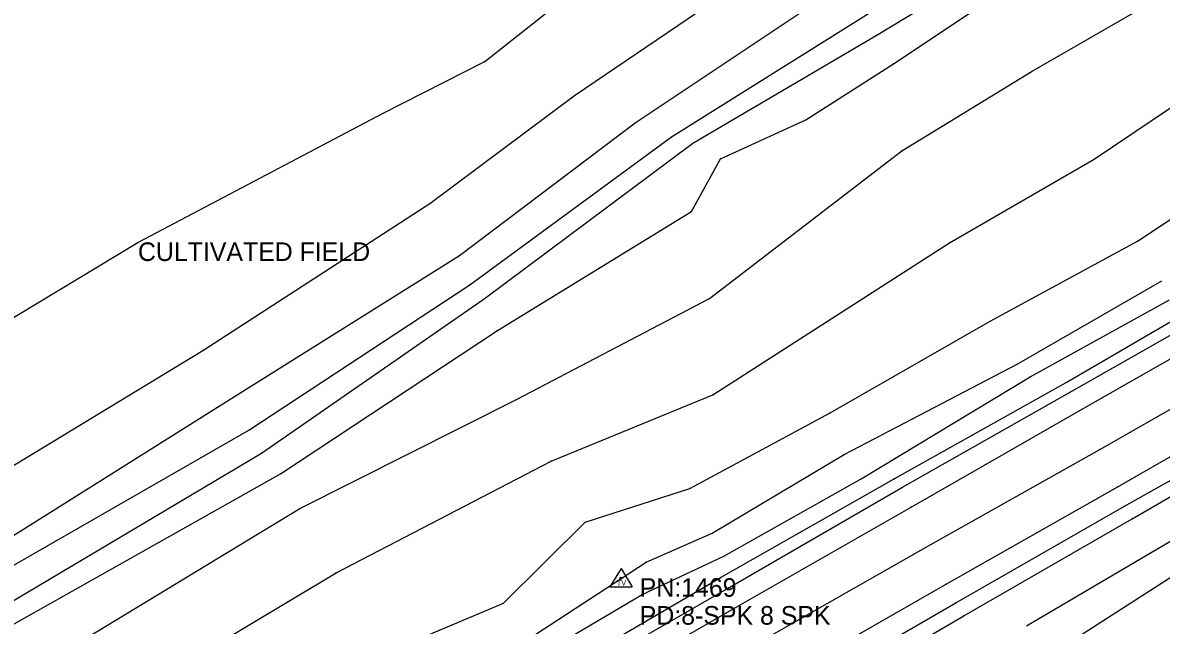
# Model space of a CAD drawing. Extents: x 1419505 to 1434054, y 1956910 to 1968644.
# Drawn here: x 1422716.6 to 1423022.6, y 1958878 to 1959040 of the extents above; entities that cross this region are included whole.
import ezdxf

# ---------------------------------------------------------------- set-up
doc = ezdxf.new("R2010")
doc.units = 0
for name, color, linetype in [('S_BREAKLINE', 7, 'Continuous'), ('S_DITCHLINE', 7, 'Continuous'), ('S_EDGE_PAVEMENT', 7, 'Continuous'), ('S_GRD_PT_SYM', 7, 'Continuous'), ('S_MSC_PT_SYM', 7, 'Continuous'), ('S_PAVEMENT_CROWN', 7, 'Continuous'), ('S_RDW_PT_SYM', 7, 'Continuous'), ('S_SECONDARY_CTL', 7, 'Continuous'), ('S_SECONDARY_CTL_ANNOT', 7, 'Continuous'), ('S_SHOULDER', 7, 'Continuous'), ('S_SURVEY_TEXT_ANNOT', 7, 'Continuous')]:
    doc.layers.add(name, color=color, linetype=linetype)

msp = doc.modelspace()

# ---------------------------------------------------------------- linework, layer by layer
at = {"layer": 'S_BREAKLINE'}
for p, q in [((1422840.7776, 1959029.6612), (1422909.3401, 1959083.9587)), ((1422864.9112, 1959020.4656), (1422927.6052, 1959063.1023)), ((1422881.2152, 1959013.1311), (1422938.3659, 1959051.3316)), ((1422950.6087, 1959028.9581), (1422978.6695, 1959047.6883)), ((1422987.9141, 1959027.032), (1423022.4534, 1959046.9853)), ((1422813.5029, 1959015.6943), (1422840.7776, 1959029.6612)), ((1422927.0872, 1959013.9382), (1422950.6087, 1959028.9581)), ((1422952.8299, 1959005.5936), (1422987.9141, 1959027.032)), ((1423004.5812, 1959003.3335), (1423034.3291, 1959023.3928)), ((1422826.0327, 1958991.4147), (1422864.9112, 1959020.4656)), ((1422747.5446, 1958980.981), (1422813.5029, 1959015.6943)), ((1422833.9622, 1958977.4928), (1422881.2152, 1959013.1311)), ((1422904.0857, 1959003.4215), (1422927.0872, 1959013.9382)), ((1422901.1935, 1958965.9291), (1422952.8299, 1959005.5936)), ((1422896.3542, 1958989.3066), (1422904.0857, 1959003.4215)), ((1422965.6687, 1958980.83), (1423004.5812, 1959003.3335)), ((1423016.171, 1958981.2871), (1423045.3818, 1959000.6413)), ((1422764.9527, 1958951.8852), (1422826.0327, 1958991.4147)), ((1422844.1579, 1958957.3105), (1422896.3542, 1958989.3066)), ((1422680.8713, 1958940.6924), (1422747.5446, 1958980.981)), ((1422902.0406, 1958939.9634), (1422965.6687, 1958980.83)), ((1422976.6254, 1958959.7677), (1423016.171, 1958981.2871)), ((1422772.8152, 1958939.0653), (1422833.9622, 1958977.4928)), ((1422983.9009, 1958948.2079), (1423022.7654, 1958970.6634)), ((1422997.0597, 1958943.3036), (1423043.5507, 1958970.5214)), ((1422849.3282, 1958938.7293), (1422901.1935, 1958965.9291)), ((1422987.3671, 1958944.8277), (1423024.7805, 1958965.546)), ((1422933.6196, 1958935.1441), (1422976.6254, 1958959.7677)), ((1422785.8341, 1958918.713), (1422844.1579, 1958957.3105)), ((1422696.1713, 1958910.1255), (1422764.9527, 1958951.8852)), ((1422937.3739, 1958923.9694), (1422983.9009, 1958948.2079)), ((1422941.9652, 1958917.4139), (1422987.3671, 1958944.8277)), ((1422950.8037, 1958917.4309), (1422997.0597, 1958943.3036)), ((1422704.0708, 1958895.8675), (1422772.8152, 1958939.0653)), ((1422791.0704, 1958909.4174), (1422849.3282, 1958938.7293)), ((1422858.6048, 1958922.1172), (1422902.0406, 1958939.9634)), ((1422895.8612, 1958914.7938), (1422933.6196, 1958935.1441)), ((1423014.7349, 1958906.6712), (1423063.781, 1958935.0261)), ((1422901.9166, 1958902.76), (1422937.3739, 1958923.9694)), ((1422800.7891, 1958892.1663), (1422858.6048, 1958922.1172)), ((1422714.3205, 1958878.4334), (1422785.8341, 1958918.713)), ((1422904.3137, 1958890.9922), (1422950.8037, 1958917.4309)), ((1422905.0308, 1958896.6186), (1422941.9652, 1958917.4139)), ((1422867.7834, 1958905.7492), (1422895.8612, 1958914.7938)), ((1422718.6307, 1958865.5316), (1422791.0704, 1958909.4174)), ((1422986.336, 1958877.8964), (1423041.4856, 1958910.3185)), ((1422845.759, 1958883.9798), (1422867.7834, 1958905.7492)), ((1422969.4989, 1958880.5795), (1423014.7349, 1958906.6712)), ((1422884.1034, 1958895.0085), (1422901.9166, 1958902.76)), ((1422990.4573, 1958868.6708), (1423043.8127, 1958903.008)), ((1422883.0484, 1958886.3259), (1422905.0308, 1958896.6186)), ((1422728.1394, 1958848.5945), (1422800.7891, 1958892.1663)), ((1422852.1924, 1958874.0641), (1422884.1034, 1958895.0085)), ((1422857.1067, 1958863.3734), (1422904.3137, 1958890.9922)), ((1422854.5305, 1958869.4648), (1422883.0484, 1958886.3259)), ((1422814.4259, 1958870.7569), (1422845.759, 1958883.9798)), ((1422923.458, 1958853.8008), (1422969.4989, 1958880.5795))]:
    msp.add_line(p, q, dxfattribs=at)
at = {"layer": 'S_DITCHLINE'}
for p, q in [((1422945.9684, 1959036.6096), (1422975.5353, 1959054.7468)), ((1422890.9719, 1959009.3679), (1422943.9453, 1959042.53)), ((1422896.7242, 1959007.7008), (1422945.9684, 1959036.6096)), ((1422836.7134, 1958969.5783), (1422890.9719, 1959009.3679)), ((1422840.5706, 1958965.7651), (1422896.7242, 1959007.7008)), ((1422777.3605, 1958930.4788), (1422836.7134, 1958969.5783)), ((1422780.7508, 1958924.2814), (1422840.5706, 1958965.7651)), ((1422706.752, 1958889.9102), (1422777.3605, 1958930.4788)), ((1422710.9763, 1958882.8447), (1422780.7508, 1958924.2814))]:
    msp.add_line(p, q, dxfattribs=at)
at = {"layer": 'S_EDGE_PAVEMENT'}
for p, q in [((1423000.534, 1958935.6891), (1423047.602, 1958962.5568)), ((1423010.6966, 1958915.1808), (1423058.3237, 1958942.5015)), ((1422955.329, 1958909.8164), (1423000.534, 1958935.6891)), ((1422964.5716, 1958888.9541), (1423010.6966, 1958915.1808)), ((1422908.352, 1958882.8477), (1422955.329, 1958909.8164)), ((1422918.8007, 1958862.7874), (1422964.5716, 1958888.9541)), ((1422859.7289, 1958855.0279), (1422908.352, 1958882.8477))]:
    msp.add_line(p, q, dxfattribs=at)
at = {"layer": 'S_GRD_PT_SYM'}
for points in [[(1422945.9684, 1959036.6096), (1422945.9684, 1959036.6596), (1422945.9684, 1959036.6096), (1422945.9184, 1959036.6096), (1422945.9684, 1959036.6096), (1422945.9684, 1959036.5596), (1422945.9684, 1959036.6096), (1422946.0184, 1959036.6096)], [(1422840.7776, 1959029.6612), (1422840.7776, 1959029.7112), (1422840.7776, 1959029.6612), (1422840.7276, 1959029.6612), (1422840.7776, 1959029.6612), (1422840.7776, 1959029.6112), (1422840.7776, 1959029.6612), (1422840.8276, 1959029.6612)], [(1422950.6087, 1959028.9581), (1422950.6087, 1959029.0081), (1422950.6087, 1959028.9581), (1422950.5587, 1959028.9581), (1422950.6087, 1959028.9581), (1422950.6087, 1959028.9081), (1422950.6087, 1959028.9581), (1422950.6587, 1959028.9581)], [(1422987.9141, 1959027.032), (1422987.9141, 1959027.082), (1422987.9141, 1959027.032), (1422987.8641, 1959027.032), (1422987.9141, 1959027.032), (1422987.9141, 1959026.982), (1422987.9141, 1959027.032), (1422987.9641, 1959027.032)], [(1422864.9112, 1959020.4656), (1422864.9112, 1959020.5156), (1422864.9112, 1959020.4656), (1422864.8612, 1959020.4656), (1422864.9112, 1959020.4656), (1422864.9112, 1959020.4156), (1422864.9112, 1959020.4656), (1422864.9612, 1959020.4656)], [(1422813.5029, 1959015.6943), (1422813.5029, 1959015.7443), (1422813.5029, 1959015.6943), (1422813.4529, 1959015.6943), (1422813.5029, 1959015.6943), (1422813.5029, 1959015.6443), (1422813.5029, 1959015.6943), (1422813.5529, 1959015.6943)], [(1422881.2152, 1959013.1311), (1422881.2152, 1959013.1811), (1422881.2152, 1959013.1311), (1422881.1652, 1959013.1311), (1422881.2152, 1959013.1311), (1422881.2152, 1959013.0811), (1422881.2152, 1959013.1311), (1422881.2652, 1959013.1311)], [(1422927.0872, 1959013.9382), (1422927.0872, 1959013.9882), (1422927.0872, 1959013.9382), (1422927.0372, 1959013.9382), (1422927.0872, 1959013.9382), (1422927.0872, 1959013.8882), (1422927.0872, 1959013.9382), (1422927.1372, 1959013.9382)], [(1422890.9719, 1959009.3679), (1422890.9719, 1959009.4179), (1422890.9719, 1959009.3679), (1422890.9219, 1959009.3679), (1422890.9719, 1959009.3679), (1422890.9719, 1959009.3179), (1422890.9719, 1959009.3679), (1422891.0219, 1959009.3679)], [(1422896.7242, 1959007.7008), (1422896.7242, 1959007.7508), (1422896.7242, 1959007.7008), (1422896.6742, 1959007.7008), (1422896.7242, 1959007.7008), (1422896.7242, 1959007.6508), (1422896.7242, 1959007.7008), (1422896.7742, 1959007.7008)], [(1422952.8299, 1959005.5936), (1422952.8299, 1959005.6436), (1422952.8299, 1959005.5936), (1422952.7799, 1959005.5936), (1422952.8299, 1959005.5936), (1422952.8299, 1959005.5436), (1422952.8299, 1959005.5936), (1422952.8799, 1959005.5936)], [(1422904.0857, 1959003.4215), (1422904.0857, 1959003.4715), (1422904.0857, 1959003.4215), (1422904.0357, 1959003.4215), (1422904.0857, 1959003.4215), (1422904.0857, 1959003.3715), (1422904.0857, 1959003.4215), (1422904.1357, 1959003.4215)], [(1423004.5812, 1959003.3335), (1423004.5812, 1959003.3835), (1423004.5812, 1959003.3335), (1423004.5312, 1959003.3335), (1423004.5812, 1959003.3335), (1423004.5812, 1959003.2835), (1423004.5812, 1959003.3335), (1423004.6312, 1959003.3335)], [(1422826.0327, 1958991.4147), (1422826.0327, 1958991.4647), (1422826.0327, 1958991.4147), (1422825.9827, 1958991.4147), (1422826.0327, 1958991.4147), (1422826.0327, 1958991.3647), (1422826.0327, 1958991.4147), (1422826.0827, 1958991.4147)], [(1422896.3542, 1958989.3066), (1422896.3542, 1958989.3566), (1422896.3542, 1958989.3066), (1422896.3042, 1958989.3066), (1422896.3542, 1958989.3066), (1422896.3542, 1958989.2566), (1422896.3542, 1958989.3066), (1422896.4042, 1958989.3066)], [(1422747.5446, 1958980.981), (1422747.5446, 1958981.031), (1422747.5446, 1958980.981), (1422747.4946, 1958980.981), (1422747.5446, 1958980.981), (1422747.5446, 1958980.931), (1422747.5446, 1958980.981), (1422747.5946, 1958980.981)], [(1422965.6687, 1958980.83), (1422965.6687, 1958980.88), (1422965.6687, 1958980.83), (1422965.6187, 1958980.83), (1422965.6687, 1958980.83), (1422965.6687, 1958980.78), (1422965.6687, 1958980.83), (1422965.7187, 1958980.83)], [(1423016.171, 1958981.2871), (1423016.171, 1958981.3371), (1423016.171, 1958981.2871), (1423016.121, 1958981.2871), (1423016.171, 1958981.2871), (1423016.171, 1958981.2371), (1423016.171, 1958981.2871), (1423016.221, 1958981.2871)], [(1422833.9622, 1958977.4928), (1422833.9622, 1958977.5428), (1422833.9622, 1958977.4928), (1422833.9122, 1958977.4928), (1422833.9622, 1958977.4928), (1422833.9622, 1958977.4428), (1422833.9622, 1958977.4928), (1422834.0122, 1958977.4928)], [(1422836.7134, 1958969.5783), (1422836.7134, 1958969.6283), (1422836.7134, 1958969.5783), (1422836.6634, 1958969.5783), (1422836.7134, 1958969.5783), (1422836.7134, 1958969.5283), (1422836.7134, 1958969.5783), (1422836.7634, 1958969.5783)], [(1422840.5706, 1958965.7651), (1422840.5706, 1958965.8151), (1422840.5706, 1958965.7651), (1422840.5206, 1958965.7651), (1422840.5706, 1958965.7651), (1422840.5706, 1958965.7151), (1422840.5706, 1958965.7651), (1422840.6206, 1958965.7651)], [(1422901.1935, 1958965.9291), (1422901.1935, 1958965.9791), (1422901.1935, 1958965.9291), (1422901.1435, 1958965.9291), (1422901.1935, 1958965.9291), (1422901.1935, 1958965.8791), (1422901.1935, 1958965.9291), (1422901.2435, 1958965.9291)], [(1422976.6254, 1958959.7677), (1422976.6254, 1958959.8177), (1422976.6254, 1958959.7677), (1422976.5754, 1958959.7677), (1422976.6254, 1958959.7677), (1422976.6254, 1958959.7177), (1422976.6254, 1958959.7677), (1422976.6754, 1958959.7677)], [(1422844.1579, 1958957.3105), (1422844.1579, 1958957.3605), (1422844.1579, 1958957.3105), (1422844.1079, 1958957.3105), (1422844.1579, 1958957.3105), (1422844.1579, 1958957.2605), (1422844.1579, 1958957.3105), (1422844.2079, 1958957.3105)], [(1422764.9527, 1958951.8852), (1422764.9527, 1958951.9352), (1422764.9527, 1958951.8852), (1422764.9027, 1958951.8852), (1422764.9527, 1958951.8852), (1422764.9527, 1958951.8352), (1422764.9527, 1958951.8852), (1422765.0027, 1958951.8852)], [(1422983.9009, 1958948.2079), (1422983.9009, 1958948.2579), (1422983.9009, 1958948.2079), (1422983.8509, 1958948.2079), (1422983.9009, 1958948.2079), (1422983.9009, 1958948.1579), (1422983.9009, 1958948.2079), (1422983.9509, 1958948.2079)], [(1422987.3671, 1958944.8277), (1422987.3671, 1958944.8777), (1422987.3671, 1958944.8277), (1422987.3171, 1958944.8277), (1422987.3671, 1958944.8277), (1422987.3671, 1958944.7777), (1422987.3671, 1958944.8277), (1422987.4171, 1958944.8277)], [(1422997.0597, 1958943.3036), (1422997.0597, 1958943.3536), (1422997.0597, 1958943.3036), (1422997.0097, 1958943.3036), (1422997.0597, 1958943.3036), (1422997.0597, 1958943.2536), (1422997.0597, 1958943.3036), (1422997.1097, 1958943.3036)], [(1422772.8152, 1958939.0653), (1422772.8152, 1958939.1153), (1422772.8152, 1958939.0653), (1422772.7652, 1958939.0653), (1422772.8152, 1958939.0653), (1422772.8152, 1958939.0153), (1422772.8152, 1958939.0653), (1422772.8652, 1958939.0653)], [(1422849.3282, 1958938.7293), (1422849.3282, 1958938.7793), (1422849.3282, 1958938.7293), (1422849.2782, 1958938.7293), (1422849.3282, 1958938.7293), (1422849.3282, 1958938.6793), (1422849.3282, 1958938.7293), (1422849.3782, 1958938.7293)], [(1422902.0406, 1958939.9634), (1422902.0406, 1958940.0134), (1422902.0406, 1958939.9634), (1422901.9906, 1958939.9634), (1422902.0406, 1958939.9634), (1422902.0406, 1958939.9134), (1422902.0406, 1958939.9634), (1422902.0906, 1958939.9634)], [(1422933.6196, 1958935.1441), (1422933.6196, 1958935.1941), (1422933.6196, 1958935.1441), (1422933.5696, 1958935.1441), (1422933.6196, 1958935.1441), (1422933.6196, 1958935.0941), (1422933.6196, 1958935.1441), (1422933.6696, 1958935.1441)], [(1422777.3605, 1958930.4788), (1422777.3605, 1958930.5288), (1422777.3605, 1958930.4788), (1422777.3105, 1958930.4788), (1422777.3605, 1958930.4788), (1422777.3605, 1958930.4288), (1422777.3605, 1958930.4788), (1422777.4105, 1958930.4788)], [(1422780.7508, 1958924.2814), (1422780.7508, 1958924.3314), (1422780.7508, 1958924.2814), (1422780.7008, 1958924.2814), (1422780.7508, 1958924.2814), (1422780.7508, 1958924.2314), (1422780.7508, 1958924.2814), (1422780.8008, 1958924.2814)], [(1422937.3739, 1958923.9694), (1422937.3739, 1958924.0194), (1422937.3739, 1958923.9694), (1422937.3239, 1958923.9694), (1422937.3739, 1958923.9694), (1422937.3739, 1958923.9194), (1422937.3739, 1958923.9694), (1422937.4239, 1958923.9694)], [(1422858.6048, 1958922.1172), (1422858.6048, 1958922.1672), (1422858.6048, 1958922.1172), (1422858.5548, 1958922.1172), (1422858.6048, 1958922.1172), (1422858.6048, 1958922.0672), (1422858.6048, 1958922.1172), (1422858.6548, 1958922.1172)], [(1422785.8341, 1958918.713), (1422785.8341, 1958918.763), (1422785.8341, 1958918.713), (1422785.7841, 1958918.713), (1422785.8341, 1958918.713), (1422785.8341, 1958918.663), (1422785.8341, 1958918.713), (1422785.8841, 1958918.713)], [(1422941.9652, 1958917.4139), (1422941.9652, 1958917.4639), (1422941.9652, 1958917.4139), (1422941.9152, 1958917.4139), (1422941.9652, 1958917.4139), (1422941.9652, 1958917.3639), (1422941.9652, 1958917.4139), (1422942.0152, 1958917.4139)], [(1422950.8037, 1958917.4309), (1422950.8037, 1958917.4809), (1422950.8037, 1958917.4309), (1422950.7537, 1958917.4309), (1422950.8037, 1958917.4309), (1422950.8037, 1958917.3809), (1422950.8037, 1958917.4309), (1422950.8537, 1958917.4309)], [(1422895.8612, 1958914.7938), (1422895.8612, 1958914.8438), (1422895.8612, 1958914.7938), (1422895.8112, 1958914.7938), (1422895.8612, 1958914.7938), (1422895.8612, 1958914.7438), (1422895.8612, 1958914.7938), (1422895.9112, 1958914.7938)], [(1422791.0704, 1958909.4174), (1422791.0704, 1958909.4674), (1422791.0704, 1958909.4174), (1422791.0204, 1958909.4174), (1422791.0704, 1958909.4174), (1422791.0704, 1958909.3674), (1422791.0704, 1958909.4174), (1422791.1204, 1958909.4174)], [(1422867.7834, 1958905.7492), (1422867.7834, 1958905.7992), (1422867.7834, 1958905.7492), (1422867.7334, 1958905.7492), (1422867.7834, 1958905.7492), (1422867.7834, 1958905.6992), (1422867.7834, 1958905.7492), (1422867.8334, 1958905.7492)], [(1423014.7349, 1958906.6712), (1423014.7349, 1958906.7212), (1423014.7349, 1958906.6712), (1423014.6849, 1958906.6712), (1423014.7349, 1958906.6712), (1423014.7349, 1958906.6212), (1423014.7349, 1958906.6712), (1423014.7849, 1958906.6712)], [(1422901.9166, 1958902.76), (1422901.9166, 1958902.81), (1422901.9166, 1958902.76), (1422901.8666, 1958902.76), (1422901.9166, 1958902.76), (1422901.9166, 1958902.71), (1422901.9166, 1958902.76), (1422901.9666, 1958902.76)], [(1422905.0308, 1958896.6186), (1422905.0308, 1958896.6686), (1422905.0308, 1958896.6186), (1422904.9808, 1958896.6186), (1422905.0308, 1958896.6186), (1422905.0308, 1958896.5686), (1422905.0308, 1958896.6186), (1422905.0808, 1958896.6186)], [(1422800.7891, 1958892.1663), (1422800.7891, 1958892.2163), (1422800.7891, 1958892.1663), (1422800.7391, 1958892.1663), (1422800.7891, 1958892.1663), (1422800.7891, 1958892.1163), (1422800.7891, 1958892.1663), (1422800.8391, 1958892.1663)], [(1422884.1034, 1958895.0085), (1422884.1034, 1958895.0585), (1422884.1034, 1958895.0085), (1422884.0534, 1958895.0085), (1422884.1034, 1958895.0085), (1422884.1034, 1958894.9585), (1422884.1034, 1958895.0085), (1422884.1534, 1958895.0085)], [(1422904.3137, 1958890.9922), (1422904.3137, 1958891.0422), (1422904.3137, 1958890.9922), (1422904.2637, 1958890.9922), (1422904.3137, 1958890.9922), (1422904.3137, 1958890.9422), (1422904.3137, 1958890.9922), (1422904.3637, 1958890.9922)], [(1422883.0484, 1958886.3259), (1422883.0484, 1958886.3759), (1422883.0484, 1958886.3259), (1422882.9984, 1958886.3259), (1422883.0484, 1958886.3259), (1422883.0484, 1958886.2759), (1422883.0484, 1958886.3259), (1422883.0984, 1958886.3259)], [(1422845.759, 1958883.9798), (1422845.759, 1958884.0298), (1422845.759, 1958883.9798), (1422845.709, 1958883.9798), (1422845.759, 1958883.9798), (1422845.759, 1958883.9298), (1422845.759, 1958883.9798), (1422845.809, 1958883.9798)], [(1422969.4989, 1958880.5795), (1422969.4989, 1958880.6295), (1422969.4989, 1958880.5795), (1422969.4489, 1958880.5795), (1422969.4989, 1958880.5795), (1422969.4989, 1958880.5295), (1422969.4989, 1958880.5795), (1422969.5489, 1958880.5795)]]:
    msp.add_lwpolyline(points, dxfattribs=at)
at = {"layer": 'S_MSC_PT_SYM'}
msp.add_lwpolyline([(1422747.5446, 1958980.981), (1422747.5446, 1958981.031), (1422747.5446, 1958980.981), (1422747.4946, 1958980.981), (1422747.5446, 1958980.981), (1422747.5446, 1958980.931), (1422747.5446, 1958980.981), (1422747.5946, 1958980.981)], dxfattribs=at)
at = {"layer": 'S_PAVEMENT_CROWN'}
for p, q in [((1423006.0693, 1958925.2984), (1423052.5453, 1958951.8302)), ((1422959.2703, 1958898.9087), (1423006.0693, 1958925.2984)), ((1422913.4393, 1958872.8881), (1422959.2703, 1958898.9087))]:
    msp.add_line(p, q, dxfattribs=at)
at = {"layer": 'S_RDW_PT_SYM'}
for points in [[(1422997.9278, 1958940.5844), (1422997.9278, 1958940.6344), (1422997.9278, 1958940.5844), (1422997.8778, 1958940.5844), (1422997.9278, 1958940.5844), (1422997.9278, 1958940.5344), (1422997.9278, 1958940.5844), (1422997.9778, 1958940.5844)], [(1423000.534, 1958935.6891), (1423000.534, 1958935.7391), (1423000.534, 1958935.6891), (1423000.484, 1958935.6891), (1423000.534, 1958935.6891), (1423000.534, 1958935.6391), (1423000.534, 1958935.6891), (1423000.584, 1958935.6891)], [(1423006.0693, 1958925.2984), (1423006.0693, 1958925.3484), (1423006.0693, 1958925.2984), (1423006.0193, 1958925.2984), (1423006.0693, 1958925.2984), (1423006.0693, 1958925.2484), (1423006.0693, 1958925.2984), (1423006.1193, 1958925.2984)], [(1422953.0589, 1958915.1508), (1422953.0589, 1958915.2008), (1422953.0589, 1958915.1508), (1422953.0089, 1958915.1508), (1422953.0589, 1958915.1508), (1422953.0589, 1958915.1008), (1422953.0589, 1958915.1508), (1422953.1089, 1958915.1508)], [(1423010.6966, 1958915.1808), (1423010.6966, 1958915.2308), (1423010.6966, 1958915.1808), (1423010.6466, 1958915.1808), (1423010.6966, 1958915.1808), (1423010.6966, 1958915.1308), (1423010.6966, 1958915.1808), (1423010.7466, 1958915.1808)], [(1422955.329, 1958909.8164), (1422955.329, 1958909.8664), (1422955.329, 1958909.8164), (1422955.279, 1958909.8164), (1422955.329, 1958909.8164), (1422955.329, 1958909.7664), (1422955.329, 1958909.8164), (1422955.379, 1958909.8164)], [(1423012.7287, 1958910.0575), (1423012.7287, 1958910.1075), (1423012.7287, 1958910.0575), (1423012.6787, 1958910.0575), (1423012.7287, 1958910.0575), (1423012.7287, 1958910.0075), (1423012.7287, 1958910.0575), (1423012.7787, 1958910.0575)], [(1422959.2703, 1958898.9087), (1422959.2703, 1958898.9587), (1422959.2703, 1958898.9087), (1422959.2203, 1958898.9087), (1422959.2703, 1958898.9087), (1422959.2703, 1958898.8587), (1422959.2703, 1958898.9087), (1422959.3203, 1958898.9087)], [(1422964.5716, 1958888.9541), (1422964.5716, 1958889.0041), (1422964.5716, 1958888.9541), (1422964.5216, 1958888.9541), (1422964.5716, 1958888.9541), (1422964.5716, 1958888.9041), (1422964.5716, 1958888.9541), (1422964.6216, 1958888.9541)], [(1422905.4188, 1958887.527), (1422905.4188, 1958887.577), (1422905.4188, 1958887.527), (1422905.3688, 1958887.527), (1422905.4188, 1958887.527), (1422905.4188, 1958887.477), (1422905.4188, 1958887.527), (1422905.4688, 1958887.527)], [(1422908.352, 1958882.8477), (1422908.352, 1958882.8977), (1422908.352, 1958882.8477), (1422908.302, 1958882.8477), (1422908.352, 1958882.8477), (1422908.352, 1958882.7977), (1422908.352, 1958882.8477), (1422908.402, 1958882.8477)], [(1422967.3768, 1958884.0138), (1422967.3768, 1958884.0638), (1422967.3768, 1958884.0138), (1422967.3268, 1958884.0138), (1422967.3768, 1958884.0138), (1422967.3768, 1958883.9638), (1422967.3768, 1958884.0138), (1422967.4268, 1958884.0138)]]:
    msp.add_lwpolyline(points, dxfattribs=at)
at = {"layer": 'S_SECONDARY_CTL'}
for p, q in [((1422877.418, 1958893.2983), (1422874.408, 1958888.3444)), ((1422877.418, 1958893.2983), (1422880.3653, 1958888.3444)), ((1422874.408, 1958888.3444), (1422880.3653, 1958888.3444))]:
    msp.add_line(p, q, dxfattribs=at)
for radius in [0.3111, 0.1827, 0.1033]:
    msp.add_circle((1422877.418, 1958890.6882), radius, dxfattribs=at)
at = {"layer": 'S_SHOULDER'}
for p, q in [((1422997.9278, 1958940.5844), (1423045.7429, 1958967.8362)), ((1422953.0589, 1958915.1508), (1422997.9278, 1958940.5844)), ((1423012.7287, 1958910.0575), (1423061.4729, 1958937.5392)), ((1422905.4188, 1958887.527), (1422953.0589, 1958915.1508)), ((1422967.3768, 1958884.0138), (1423012.7287, 1958910.0575)), ((1422858.8438, 1958860.8883), (1422905.4188, 1958887.527)), ((1422921.5629, 1958857.7121), (1422967.3768, 1958884.0138))]:
    msp.add_line(p, q, dxfattribs=at)

# ---------------------------------------------------------------- texts
at = {"layer": 'S_SECONDARY_CTL'}
msp.add_text('TV', height=1.5, rotation=360, dxfattribs=at).set_placement((1422876.2133, 1958888.6769))
at = {"layer": 'S_SECONDARY_CTL_ANNOT'}
for s, p in [('PN:1469', (1422882.418, 1958885.6882)), ('PD:8-SPK 8 SPK', (1422882.418, 1958878.1882))]:
    msp.add_text(s, height=5, dxfattribs=at).set_placement(p)
at = {"layer": 'S_SURVEY_TEXT_ANNOT'}
msp.add_text('CULTIVATED FIELD', height=5, dxfattribs=at).set_placement((1422747.5446, 1958975.981))

doc.saveas('drawing.dxf')
